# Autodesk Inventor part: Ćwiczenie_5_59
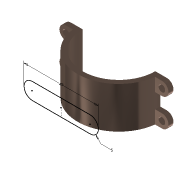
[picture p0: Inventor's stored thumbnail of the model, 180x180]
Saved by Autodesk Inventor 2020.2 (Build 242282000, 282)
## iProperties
Created: 2005-06
Part Number: Ćwiczenie_5_59
Document SubType Name: Modeling
Designer: F.Stasiak
Manufacturer: Standard
Standards Organization: Custom
Density: 1 g/cm^3
Material: Ogólny
Appearance: Brąz armatni - antyczny - polerowany
Manager: www.cadconsulting.pl
Company: Fabian Stasiak CAD Consulting
Author: F.Stasiak
Subject: Zbiór ćwiczeń. Autodesk Inventor 2020. Kurs podstawowy
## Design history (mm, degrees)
sketch "Szkic1"
  geometry: L1 (-25, 0)-(25, 0); A1 r 25 centre (0, 0) between (25, 0) and (-25, 0); 2 further points
  constraints: 2 coincident, 2 end point, 2 point on circle, 1 centre point, 1 horizontal, 1 midpoint
  dimensions: "d0" = 50 distance of L1.start L1.end
extrude "Wyciągnięcie proste1" new body sketch "Szkic1" stored distance "d1" = 25; taper "d2" = 0 deg
feature "Skorupa1" dims "d6" = 3
sketch "Szkic3"
  geometry: L1 (22, -12.5)-(22, 12.5) reference; L2 (-22, 12.5)-(-22, -12.5) reference; L3 (-22, 12.5)-(-29, 12.5); L4 (-29, 4.5)-(-22, 4.5); L5 (-22, -12.5)-(-29, -12.5); L6 (-29, -4.5)-(-22, -4.5); C1 r 2 at (-29, 8.5); C2 r 2 at (-29, -8.5); A1 r 4 centre (-29, 8.5) between (-29, 12.5) and (-29, 4.5); A2 r 4 centre (-29, -8.5) between (-29, -4.5) and (-29, -12.5)
  constraints: 8 end point, 4 centre point, 4 point on circle, 4 tangent, 3 parallel, 2 coincident, 2 equal radius, 2 perpendicular, 2 point on line
  dimensions: "d7" = 4 radius of A1; "d8" = 7 distance of L2.start L3.end; "d9" = 4 diameter of C1
extrude "Wyciągnięcie proste2" join sketch "Szkic3" distance "d10" = 3; taper "d11" = 0 deg
mirror "Lustro1"
node "Płaszczyzna konstrukcyjna1"
sketch "Szkic2"
  geometry: L1 (-17.5, 5)-(17.5, 5); L2 (17.5, -5)-(-17.5, -5); L3 (0, 5)-(0, -5); A1 r 5 centre (17.5, 0) between (17.5, -5) and (17.5, 5); A2 r 5 centre (-17.5, 0) between (-17.5, 5) and (-17.5, -5); 2 further points
  constraints: 6 end point, 4 point on circle, 4 tangent, 3 midpoint, 2 centre point, 1 coincident, 1 horizontal, 1 parallel
  dimensions: "d4" = 45 dimension on A1 A2; "d5" = 5 radius of A1
node "Bryła1"
node "Korpusy bryłowe"
node "Korpusy powierzchniowe"
other parameters: "d3" = 35
